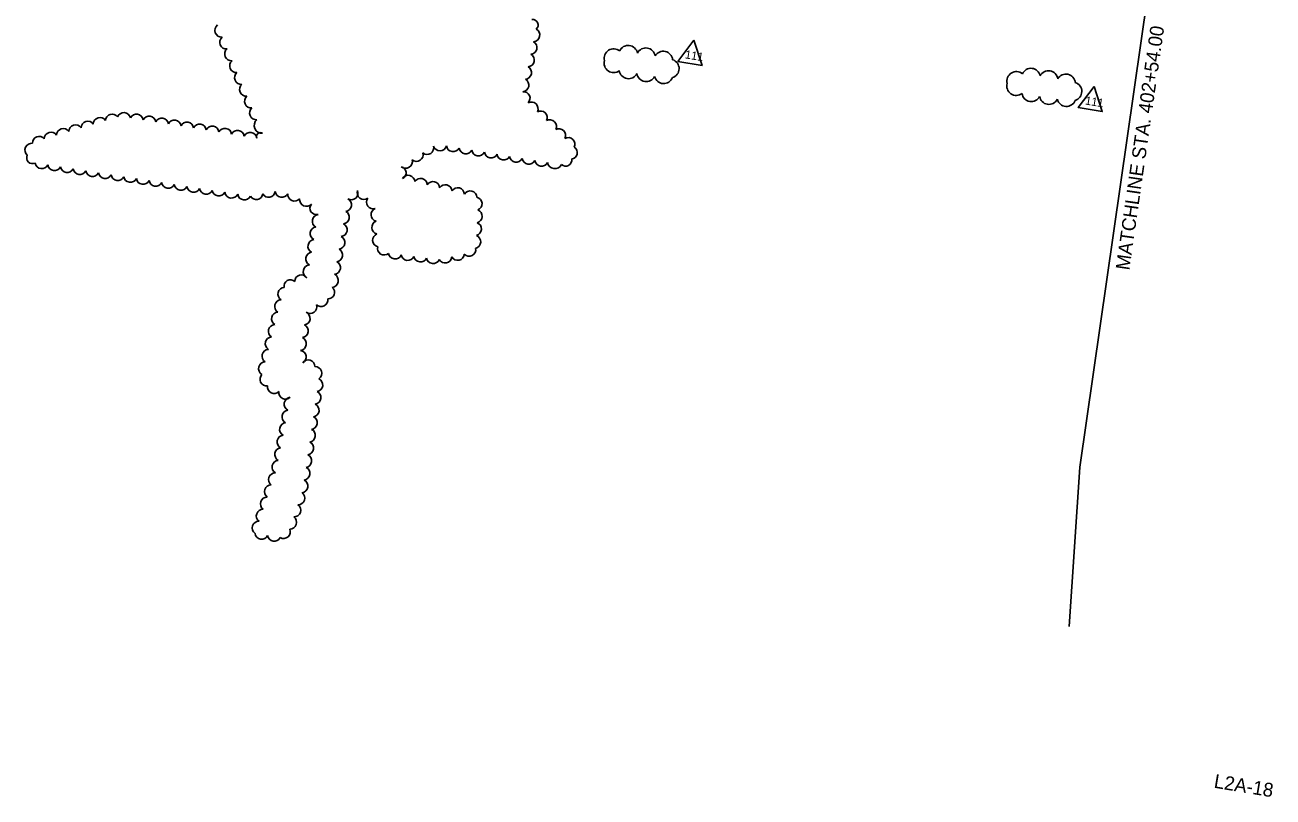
# Model space of a CAD drawing. Extents: x 927483 to 928746, y 636242 to 637203.
# Drawn here: x 928011 to 928733, y 636242 to 636688 of the extents above; entities that cross this region are included whole.
import ezdxf

# ---------------------------------------------------------------- set-up
doc = ezdxf.new("R2010")
doc.units = 0
for name, color, linetype in [('Cloud_dp', 7, 'Continuous'), ('MatchLines_dp', 7, 'Continuous'), ('TextShtNo', 7, 'Continuous')]:
    doc.layers.add(name, color=color, linetype=linetype)

msp = doc.modelspace()

# ---------------------------------------------------------------- linework, layer by layer
at = {"layer": 'Cloud_dp'}
for points in [[(928397.88, 636679.08), (928388.73, 636666.84), (928402.63, 636664.55)], [(928629.2, 636652.42), (928620.05, 636640.18), (928633.94, 636637.89)]]:
    msp.add_lwpolyline(points, close=True, dxfattribs=at)
for centre, radius, start, end in [((928304.71, 636687.92), 3.17, 312.00903, 97.00903), ((928125, 636684.79), 3.96, 128.01175, 273.01175), ((928304.88, 636682.13), 3.95, 275.37317, 60.37317), ((928127.72, 636677.88), 3.88, 130.378, 275.378), ((928303.33, 636674.83), 3.88, 275.37317, 60.37317), ((928130.59, 636671.07), 3.88, 130.378, 275.378), ((928301.78, 636667.6), 3.88, 275.37317, 60.37317), ((928351.52, 636668.73), 5.42, 49.77309, 194.77309), ((928359.97, 636670.65), 5.42, 10.81232, 155.81232), ((928370.14, 636669.22), 5.42, 8.20535, 153.20535), ((928380.22, 636667.31), 5.42, 5.2898, 150.2898), ((928133.46, 636664.26), 3.88, 130.378, 275.378), ((928300.22, 636660.38), 3.88, 275.37317, 60.37317), ((928351.47, 636665.78), 5.42, 163.13084, 308.13084), ((928383.96, 636662.65), 5.42, 287.14219, 72.14219), ((928592.73, 636657.44), 5.42, 10.81232, 155.81232), ((928136.34, 636657.44), 3.88, 130.378, 275.378), ((928298.67, 636653.15), 3.88, 275.37317, 60.37317), ((928360.18, 636662.28), 5.42, 188.13813, 333.13813), ((928370.39, 636660.6), 5.42, 188.21634, 333.21634), ((928380.5, 636659.45), 5.42, 193.70912, 338.70912), ((928584.28, 636655.52), 5.42, 49.77309, 194.77309), ((928602.89, 636656.01), 5.42, 8.20535, 153.20535), ((928612.97, 636654.1), 5.42, 5.2898, 150.2898), ((928616.71, 636649.44), 5.42, 287.14219, 72.14219), ((928139.21, 636650.63), 3.88, 130.378, 275.378), ((928299.55, 636645.62), 3.7, 312.97729, 97.97729), ((928584.22, 636652.57), 5.42, 163.13084, 308.13084), ((928592.94, 636649.07), 5.42, 188.13813, 333.13813), ((928142.09, 636643.82), 3.88, 130.378, 275.378), ((928303.94, 636639.48), 3.91, 333.53608, 118.53608), ((928603.15, 636647.39), 5.42, 188.21634, 333.21634), ((928613.26, 636646.24), 5.42, 193.70912, 338.70912), ((928054.64, 636630.49), 3.88, 34.15139, 179.15139), ((928061.63, 636632.61), 3.78, 34.15139, 179.15139), ((928068.43, 636633.3), 3.95, 13.66391, 158.66391), ((928075.73, 636632.5), 3.88, 8.41234, 153.41234), ((928083.03, 636631.33), 3.88, 8.41234, 153.41234), ((928090.33, 636630.16), 3.88, 8.41234, 153.41234), ((928144.96, 636637.01), 3.88, 130.378, 275.378), ((928148.22, 636629.75), 4.46, 130.378, 275.378), ((928309.29, 636634.33), 3.88, 333.53608, 118.53608), ((928314.61, 636629.2), 3.88, 333.53608, 118.53608), ((928026.31, 636622.02), 3.88, 34.15139, 179.15139), ((928033.39, 636624.14), 3.88, 34.15139, 179.15139), ((928040.47, 636626.26), 3.88, 34.15139, 179.15139), ((928047.56, 636628.37), 3.88, 34.15139, 179.15139), ((928097.63, 636628.99), 3.88, 8.41234, 153.41234), ((928104.93, 636627.82), 3.88, 8.41234, 153.41234), ((928112.24, 636626.66), 3.88, 8.41234, 153.41234), ((928119.54, 636625.49), 3.88, 8.41234, 153.41234), ((928126.84, 636624.32), 3.88, 8.41234, 153.41234), ((928134.14, 636623.15), 3.88, 8.41234, 153.41234), ((928141.44, 636621.99), 3.88, 8.41234, 153.41234), ((928319.93, 636624.07), 3.88, 333.53608, 118.53608), ((928015.18, 636615.62), 3.92, 83.55884, 228.55884), ((928019.43, 636619.72), 3.81, 38.13996, 183.13996), ((928147.39, 636623.4), 2.28, 56.78371, 201.78371), ((928325.25, 636618.94), 3.88, 333.53608, 118.53608), ((928015.63, 636611.12), 3.41, 152.83352, 297.83352), ((928237.54, 636612.94), 3.88, 230.11358, 15.11358), ((928243.73, 636616.88), 3.82, 230.11358, 15.11358), ((928251.12, 636619.12), 3.91, 198.57156, 343.57156), ((928258.75, 636618.56), 3.91, 188.0807, 333.0807), ((928266.08, 636617.34), 3.88, 188.0807, 333.0807), ((928273.37, 636616.13), 3.88, 188.0807, 333.0807), ((928280.66, 636614.92), 3.88, 188.0807, 333.0807), ((928287.96, 636613.71), 3.88, 188.0807, 333.0807), ((928295.25, 636612.5), 3.88, 188.0807, 333.0807), ((928326.94, 636614.08), 3.6, 275.32918, 60.32918), ((928021.05, 636608.69), 3.88, 188.72433, 333.72433), ((928028.36, 636607.56), 3.88, 188.72433, 333.72433), ((928035.67, 636606.44), 3.88, 188.72433, 333.72433), ((928042.97, 636605.31), 3.88, 188.72433, 333.72433), ((928231.28, 636608.95), 3.91, 230.11358, 15.11358), ((928228.05, 636602.45), 3.57, 293.18442, 78.18442), ((928302.54, 636611.29), 3.88, 188.0807, 333.0807), ((928309.84, 636610.08), 3.88, 188.0807, 333.0807), ((928317.49, 636609.1), 4.27, 190.52798, 335.52798), ((928323.83, 636609.84), 3.51, 225.67641, 10.67641), ((928050.28, 636604.18), 3.88, 188.72433, 333.72433), ((928057.59, 636603.05), 3.88, 188.72433, 333.72433), ((928064.89, 636601.92), 3.88, 188.72433, 333.72433), ((928072.2, 636600.8), 3.88, 188.72433, 333.72433), ((928079.51, 636599.67), 3.88, 188.72433, 333.72433), ((928086.81, 636598.54), 3.88, 188.72433, 333.72433), ((928232.75, 636597.14), 3.88, 3.38558, 148.38558), ((928239.92, 636595.33), 3.88, 3.38558, 148.38558), ((928247.09, 636593.53), 3.88, 3.38558, 148.38558), ((928094.12, 636597.41), 3.88, 188.72433, 333.72433), ((928101.42, 636596.28), 3.88, 188.72433, 333.72433), ((928108.73, 636595.16), 3.88, 188.72433, 333.72433), ((928116.04, 636594.03), 3.88, 188.72433, 333.72433), ((928123.34, 636592.9), 3.88, 188.72433, 333.72433), ((928130.7, 636591.78), 3.93, 188.72433, 333.72433), ((928138.12, 636590.66), 3.94, 189.00402, 334.00402), ((928144.96, 636590.73), 3.76, 208.4841, 353.4841), ((928152.07, 636592.13), 3.83, 208.4841, 353.4841), ((928159.77, 636592.2), 3.92, 187.48416, 332.48416), ((928167.1, 636589.97), 3.88, 173.76412, 318.76412), ((928199.95, 636590.72), 3.82, 238.39093, 23.39093), ((928207.12, 636590.99), 3.88, 161.11171, 306.11171), ((928254.26, 636591.73), 3.88, 3.38558, 148.38558), ((928261.43, 636589.92), 3.88, 3.38558, 148.38558), ((928268.6, 636588.12), 3.88, 3.38558, 148.38558), ((928173.89, 636586.99), 3.9, 173.76412, 318.76412), ((928179.72, 636582.03), 3.75, 140.47119, 285.47119), ((928196.16, 636584.03), 3.88, 277.50194, 62.50194), ((928212.52, 636585.55), 3.87, 143.57759, 288.57759), ((928271.59, 636584.58), 3.87, 291.81437, 76.81437), ((928181.23, 636574.58), 3.88, 97.64151, 242.64151), ((928194.88, 636576.75), 3.88, 277.50194, 62.50194), ((928215.16, 636578.27), 3.88, 111.15199, 256.15199), ((928271.65, 636577.37), 3.88, 284.27199, 69.27199), ((928179.97, 636567.3), 3.88, 97.64151, 242.64151), ((928193.59, 636569.47), 3.88, 277.50194, 62.50194), ((928215.63, 636570.89), 3.88, 111.15199, 256.15199), ((928271.24, 636569.99), 3.88, 284.27199, 69.27199), ((928178.7, 636560.01), 3.88, 97.64151, 242.64151), ((928192.31, 636562.19), 3.88, 277.50194, 62.50194), ((928216.1, 636563.51), 3.88, 111.15199, 256.15199), ((928270.81, 636562.58), 3.91, 284.27199, 69.27199), ((928177.43, 636552.73), 3.88, 97.64151, 242.64151), ((928191.03, 636554.91), 3.88, 277.50194, 62.50194), ((928218.89, 636558.79), 3.84, 165.56897, 310.56897), ((928225.2, 636556.59), 3.88, 190.59185, 335.59185), ((928232.54, 636555.7), 3.88, 190.59185, 335.59185), ((928239.88, 636554.81), 3.88, 190.59185, 335.59185), ((928254.13, 636554.2), 3.86, 209.1992, 354.1992), ((928261.33, 636555.74), 3.88, 209.91227, 354.91227), ((928267.95, 636558.13), 3.88, 224.74932, 9.74932), ((928176.08, 636545.32), 3.98, 96.07948, 241.07948), ((928189.74, 636547.63), 3.88, 277.50194, 62.50194), ((928247.22, 636553.92), 3.88, 190.59185, 335.59185), ((928164.69, 636536.97), 3.64, 46.74778, 191.74778), ((928171.02, 636539.63), 3.83, 35.12478, 180.12478), ((928188.39, 636540.22), 4.03, 277.50194, 62.50194), ((928161.34, 636532.36), 3.88, 93.13574, 238.13574), ((928186.56, 636533.34), 3.72, 265.78538, 50.78538), ((928159.51, 636525.2), 3.88, 93.13574, 238.13574), ((928176.13, 636524.94), 3.83, 234.37083, 19.37083), ((928182.48, 636528.95), 3.87, 225.05425, 10.05425), ((928157.67, 636518.04), 3.88, 93.13574, 238.13574), ((928172.19, 636518.34), 3.88, 279.02886, 64.02886), ((928155.84, 636510.88), 3.88, 93.13574, 238.13574), ((928171.11, 636511.03), 3.88, 279.02886, 64.02886), ((928154, 636503.71), 3.88, 93.13574, 238.13574), ((928169.98, 636503.65), 3.96, 279.02886, 64.02886), ((928152.17, 636496.55), 3.88, 93.13574, 238.13574), ((928170.1, 636496), 3.77, 297.3363, 82.3363), ((928150.34, 636489.26), 4.01, 93.13574, 238.13574), ((928174.99, 636490.47), 3.84, 0.36741, 145.36741), ((928178.91, 636486.57), 3.92, 306.01777, 91.01777), ((928150.86, 636483.14), 3.77, 134.14669, 279.14669), ((928179.52, 636479.92), 3.88, 279.19803, 64.19803), ((928155.28, 636478.78), 3.88, 170.5053, 315.5053), ((928161.82, 636475.43), 3.83, 170.5053, 315.5053), ((928178.46, 636472.6), 3.88, 279.19803, 64.19803), ((928165.09, 636468.83), 3.96, 97.92253, 242.92253), ((928177.39, 636465.28), 3.88, 279.19803, 64.19803), ((928163.73, 636461.45), 3.88, 96.51447, 241.51447), ((928176.32, 636457.97), 3.88, 279.19803, 64.19803), ((928162.32, 636454.19), 3.88, 96.51447, 241.51447), ((928175.25, 636450.65), 3.88, 279.19803, 64.19803), ((928160.91, 636446.94), 3.88, 96.51447, 241.51447), ((928174.19, 636443.34), 3.88, 279.19803, 64.19803), ((928159.5, 636439.68), 3.88, 96.51447, 241.51447), ((928173.12, 636436.02), 3.88, 279.19803, 64.19803), ((928157.97, 636432.41), 3.87, 94.73177, 239.73177), ((928172.05, 636428.7), 3.88, 279.19803, 64.19803), ((928155.95, 636425.19), 3.88, 88.91648, 233.91648), ((928170.92, 636421.42), 3.87, 278.08863, 63.08863), ((928153.59, 636418.18), 3.88, 88.91648, 233.91648), ((928169.16, 636414.47), 3.88, 268.61694, 53.61694), ((928151.23, 636411.17), 3.88, 88.91648, 233.91648), ((928166.77, 636407.47), 3.88, 268.61694, 53.61694), ((928148.88, 636404.16), 3.88, 88.91648, 233.91648), ((928164.37, 636400.47), 3.89, 268.61694, 53.61694), ((928146.52, 636397.16), 3.88, 88.91648, 233.91648), ((928160.77, 636394.96), 3.86, 239.82016, 24.82016), ((928148.08, 636394.57), 3.88, 188.13813, 333.13813), ((928155.37, 636393.37), 3.88, 188.13813, 333.13813)]:
    msp.add_arc(centre, radius, start, end, dxfattribs=at)
at = {"layer": 'MatchLines_dp'}
for p, q in [((928693.09, 636933.47), (928620.98, 636432.26)), ((928620.98, 636432.26), (928614.87, 636340.32))]:
    msp.add_line(p, q, dxfattribs=at)

# ---------------------------------------------------------------- texts
at = {"layer": 'Cloud_dp'}
for p in [(928392.49, 636668.67), (928623.8, 636642.01)]:
    msp.add_text('111', height=4.8, rotation=350.63813, dxfattribs=at).set_placement(p)
at = {"layer": 'MatchLines_dp'}
msp.add_text('MATCHLINE STA. 402+54.00', height=8, rotation=81.81299, dxfattribs=at).set_placement((928649.58, 636545.86))
at = {"layer": 'TextShtNo'}
msp.add_text('L2A-18', height=8, rotation=350.63813, dxfattribs=at).set_placement((928698.13, 636247.11))

doc.saveas('drawing.dxf')
